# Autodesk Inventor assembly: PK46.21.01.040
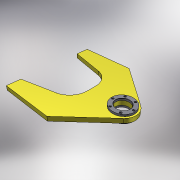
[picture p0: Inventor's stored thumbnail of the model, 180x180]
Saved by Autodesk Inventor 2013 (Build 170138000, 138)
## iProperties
Created: 2005-04
Part Number: PK46.21.01.040
Document SubType Name: Assembly
Designer: salex
Manufacturer: Standard
Standards Organization: Custom
Author: salex
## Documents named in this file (3)
- C:\Product Design Suite 2013 Test Drive\Dynamic Simulation\Workspace\Assy, Chassis, Front\PK46.21.01.040.iam
- C:\Product Design Suite 2013 Test Drive\Dynamic Simulation\Workspace\Assy, Chassis, Front\PK46.21.01.008.ipt
- C:\Product Design Suite 2013 Test Drive\Dynamic Simulation\Workspace\Assy, Chassis, Front\PK46.21.01.009.ipt
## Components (3 placed, 2 different names)
1. PK46.21.01.008:1 — Вставка:1, Вставка:2, Заподлицо:1
2. PK46.21.01.009:1 — Вставка:1
3. PK46.21.01.009:2 — Вставка:2
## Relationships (3: Insert 2, Flush 1)
- Вставка:1 [Insert]: PK46.21.01.008:1 ↔ PK46.21.01.009:1
- Вставка:2 [Insert]: PK46.21.01.008:1 ↔ PK46.21.01.009:2
- Заподлицо:1 [Flush]: PK46.21.01.008:1
